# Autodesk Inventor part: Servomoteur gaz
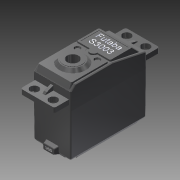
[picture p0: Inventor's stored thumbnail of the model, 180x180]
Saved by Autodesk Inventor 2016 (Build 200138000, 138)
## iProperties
Shininess: 20.0
Angle Display Precision: 2
Document Length Units: 11270
Document Angle Units: 11279
Document Time Units: 11290
Document Mass Units: 11283
Document Length Units Precision: 3
Document Angle Units Precision: 2
Compacted: True
Created: 2002-09
Part Number: Servomoteur gaz
Material: Générique
Document SubType Name: Modélisation
Designer: GAUTHERON
Density: 1 g/cm^3
Appearance: Plastique (Noir)
Density: 0.0
Volumn: 0.0
Area: 0.0
PropertySet Name: Model Information
Control State: 0
Master: False
Checked Out: False
Author: GAUTHERON
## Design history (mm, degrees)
feature "Base1"
sketch "Esquisse1"
  geometry: L1 (15.68, 0)-(0, 0) reference; L2 (1.757, -3.791)-(1.757, -0.791); L3 (1.757, -0.791)-(3.757, -0.791); L4 (3.757, -0.791)-(3.757, -1.139); L5 (3.757, -1.139)-(2.148, -1.139); L6 (2.148, -1.139)-(2.148, -2.096); L7 (2.148, -2.096)-(3.496, -2.096); L8 (3.496, -2.096)-(3.496, -2.443); L9 (3.496, -2.443)-(2.148, -2.443); L10 (2.148, -2.443)-(2.148, -3.791); L11 (2.148, -3.791)-(1.757, -3.791); L12 (5.583, -3.791)-(5.583, -3.437); L13 (4.278, -2.961)-(4.278, -1.617); L14 (4.278, -1.617)-(4.67, -1.617); L15 (4.67, -1.617)-(4.67, -2.8); L16 (5.583, -2.76)-(5.583, -1.617); L17 (5.583, -1.617)-(5.974, -1.617); L18 (5.974, -1.617)-(5.974, -3.791); L19 (5.974, -3.791)-(5.583, -3.791); L20 (7.365, -3.477)-(7.409, -3.801); L21 (6.626, -3.185)-(6.626, -1.965); L22 (6.626, -1.965)-(6.365, -1.965); L23 (6.365, -1.965)-(6.365, -1.617); L24 (6.365, -1.617)-(6.626, -1.617); L25 (6.626, -1.617)-(6.626, -1.081); L26 (6.626, -1.081)-(7.018, -0.861); L27 (7.018, -0.861)-(7.018, -1.617); L28 (7.018, -1.617)-(7.365, -1.617); L29 (7.365, -1.617)-(7.365, -1.965); L30 (7.365, -1.965)-(7.018, -1.965); L31 (7.018, -1.965)-(7.018, -3.195); L32 (8.061, -2.269)-(7.67, -2.226); L33 (9.452, -2.381)-(9.452, -2.848); L34 (9.583, -3.791)-(9.192, -3.791); L35 (9.016, -2.861)-(9.018, -2.748); L36 (10.409, -3.791)-(10.018, -3.791); L37 (10.018, -3.791)-(10.018, -0.791); L38 (10.018, -0.791)-(10.409, -0.791); L39 (10.409, -0.791)-(10.409, -1.91); L40 (10.409, -3.466)-(10.409, -3.791); L41 (12.67, -2.269)-(12.278, -2.226); L42 (14.061, -2.381)-(14.061, -2.848); L43 (14.192, -3.791)-(13.8, -3.791); L44 (13.624, -2.861)-(13.626, -2.748); 147 further points
  constraints: 86 end point, 215 other
extrude "Extrusion1" cut sketch "Esquisse1" distance "d0" = 1; taper "d1" = 0 deg
sketch "Esquisse2"
  geometry: L1 (15.042, -8.045)-(0.64, -8.045) reference; L2 (1.991, -7.001)-(2.383, -7.001); L3 (4.252, -5.915)-(3.861, -5.915); L4 (4.731, -7.262)-(5.122, -7.219); L5 (5.47, -6.61)-(5.51, -6.262); L6 (5.165, -5.871)-(4.774, -5.828); L7 (11.644, -7.262)-(12.035, -7.219); L8 (12.383, -6.61)-(12.423, -6.262); L9 (12.078, -5.871)-(11.687, -5.828); 184 further points
  constraints: 16 end point, 3 point on line, 251 other
extrude "Extrusion2" cut sketch "Esquisse2" distance "d2" = 1; taper "d3" = 0 deg
sketch "Esquisse3"
  geometry: L1 (0, 0)-(14.402, 0) reference; L2 (14.652, 0.25)-(14.652, 2.55) reference; L3 (14.402, 2.8)-(0, 2.8) reference; L4 (-0.25, 2.55)-(-0.25, 0.25) reference; L5 (6.613, 0.723)-(5.62, 0.723) reference; L6 (5.62, 0.723)-(5.62, 0.87) reference; L7 (5.62, 0.87)-(6.027, 0.87) reference; L8 (6.027, 0.87)-(6.027, 1.992) reference; L9 (6.027, 1.992)-(6.206, 1.992) reference; L10 (6.206, 1.992)-(6.206, 0.87) reference; L11 (6.206, 0.87)-(6.613, 0.87) reference; L12 (6.613, 0.87)-(6.613, 0.723) reference; L13 (5.409, 1.992)-(5.599, 1.992) reference; L14 (5.599, 1.992)-(5.095, 0.723) reference; L15 (5.095, 0.723)-(4.893, 0.723) reference; L16 (4.893, 0.723)-(4.39, 1.992) reference; L17 (4.39, 1.992)-(4.58, 1.992) reference; L18 (4.58, 1.992)-(4.724, 1.602) reference; L19 (4.724, 1.602)-(5.265, 1.602) reference; L20 (5.265, 1.602)-(5.409, 1.992) reference; L21 (0.709, 1.992)-(0.888, 1.992) reference; L22 (0.888, 1.992)-(0.888, 0.723) reference; L23 (0.888, 0.723)-(0.699, 0.723) reference; L24 (0.699, 0.723)-(0.091, 1.67) reference; L25 (0.091, 1.67)-(0.091, 0.723) reference; L26 (0.091, 0.723)-(-0.088, 0.723) reference; L27 (-0.088, 0.723)-(-0.088, 1.992) reference; L28 (-0.088, 1.992)-(0.101, 1.992) reference; L29 (0.101, 1.992)-(0.709, 1.045) reference; L30 (0.709, 1.045)-(0.709, 1.992) reference; L31 (2.042, 1.992)-(2.232, 1.992) reference; L32 (2.232, 1.992)-(1.729, 0.723) reference; L33 (1.729, 0.723)-(1.527, 0.723) reference; L34 (1.527, 0.723)-(1.023, 1.992) reference; L35 (1.023, 1.992)-(1.213, 1.992) reference; L36 (1.213, 1.992)-(1.357, 1.602) reference; L37 (1.357, 1.602)-(1.898, 1.602) reference; L38 (1.898, 1.602)-(2.042, 1.992) reference; L39 (3.365, 1.992)-(3.577, 1.992) reference; L40 (3.577, 1.992)-(3.896, 0.723) reference; L41 (3.896, 0.723)-(3.712, 0.723) reference; L42 (3.712, 0.723)-(3.523, 1.558) reference; L43 (3.4, 1.589)-(3.15, 0.723) reference; L44 (3.15, 0.723)-(2.934, 0.723) reference; L45 (2.934, 0.723)-(2.753, 1.359) reference; L46 (2.593, 1.553)-(2.406, 0.723) reference; L47 (2.406, 0.723)-(2.221, 0.723) reference; L48 (2.221, 0.723)-(2.541, 1.992) reference; L49 (2.541, 1.992)-(2.738, 1.992) reference; L50 (2.738, 1.992)-(3.003, 1.023) reference; L51 (3.091, 1.043)-(3.365, 1.992) reference; L52 (4.059, 1.992)-(4.238, 1.992) reference; L53 (4.238, 1.992)-(4.238, 0.723) reference; L54 (4.238, 0.723)-(4.059, 0.723) reference; L55 (4.059, 0.723)-(4.059, 1.992) reference; L56 (8.082, 0.723)-(7.475, 1.67) reference; L57 (7.475, 1.67)-(7.475, 0.723) reference; L58 (7.475, 0.723)-(7.296, 0.723) reference; L59 (7.296, 0.723)-(7.296, 1.992) reference; L60 (7.296, 1.992)-(7.485, 1.992) reference; L61 (7.485, 1.992)-(8.093, 1.045) reference; L62 (8.093, 1.045)-(8.093, 1.992) reference; L63 (8.093, 1.992)-(8.271, 1.992) reference; L64 (8.271, 1.992)-(8.271, 0.723) reference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; A1 r 0.25 centre (14.402, 0.25) between (14.402, 0) and (14.652, 0.25) reference; A2 r 0.25 centre (14.402, 2.55) between (14.652, 2.55) and (14.402, 2.8) reference; A3 r 0.25 centre (0, 2.55) between (0, 2.8) and (-0.25, 2.55) reference; A4 r 0.25 centre (0, 0.25) between (-0.25, 0.25) and (0, 0) reference; 7 further points
  constraints: 12 other
node "Solide1"
node "Corps solides"
node "Corps surfaciques"
